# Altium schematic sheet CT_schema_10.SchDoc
size 389 x 278 mm
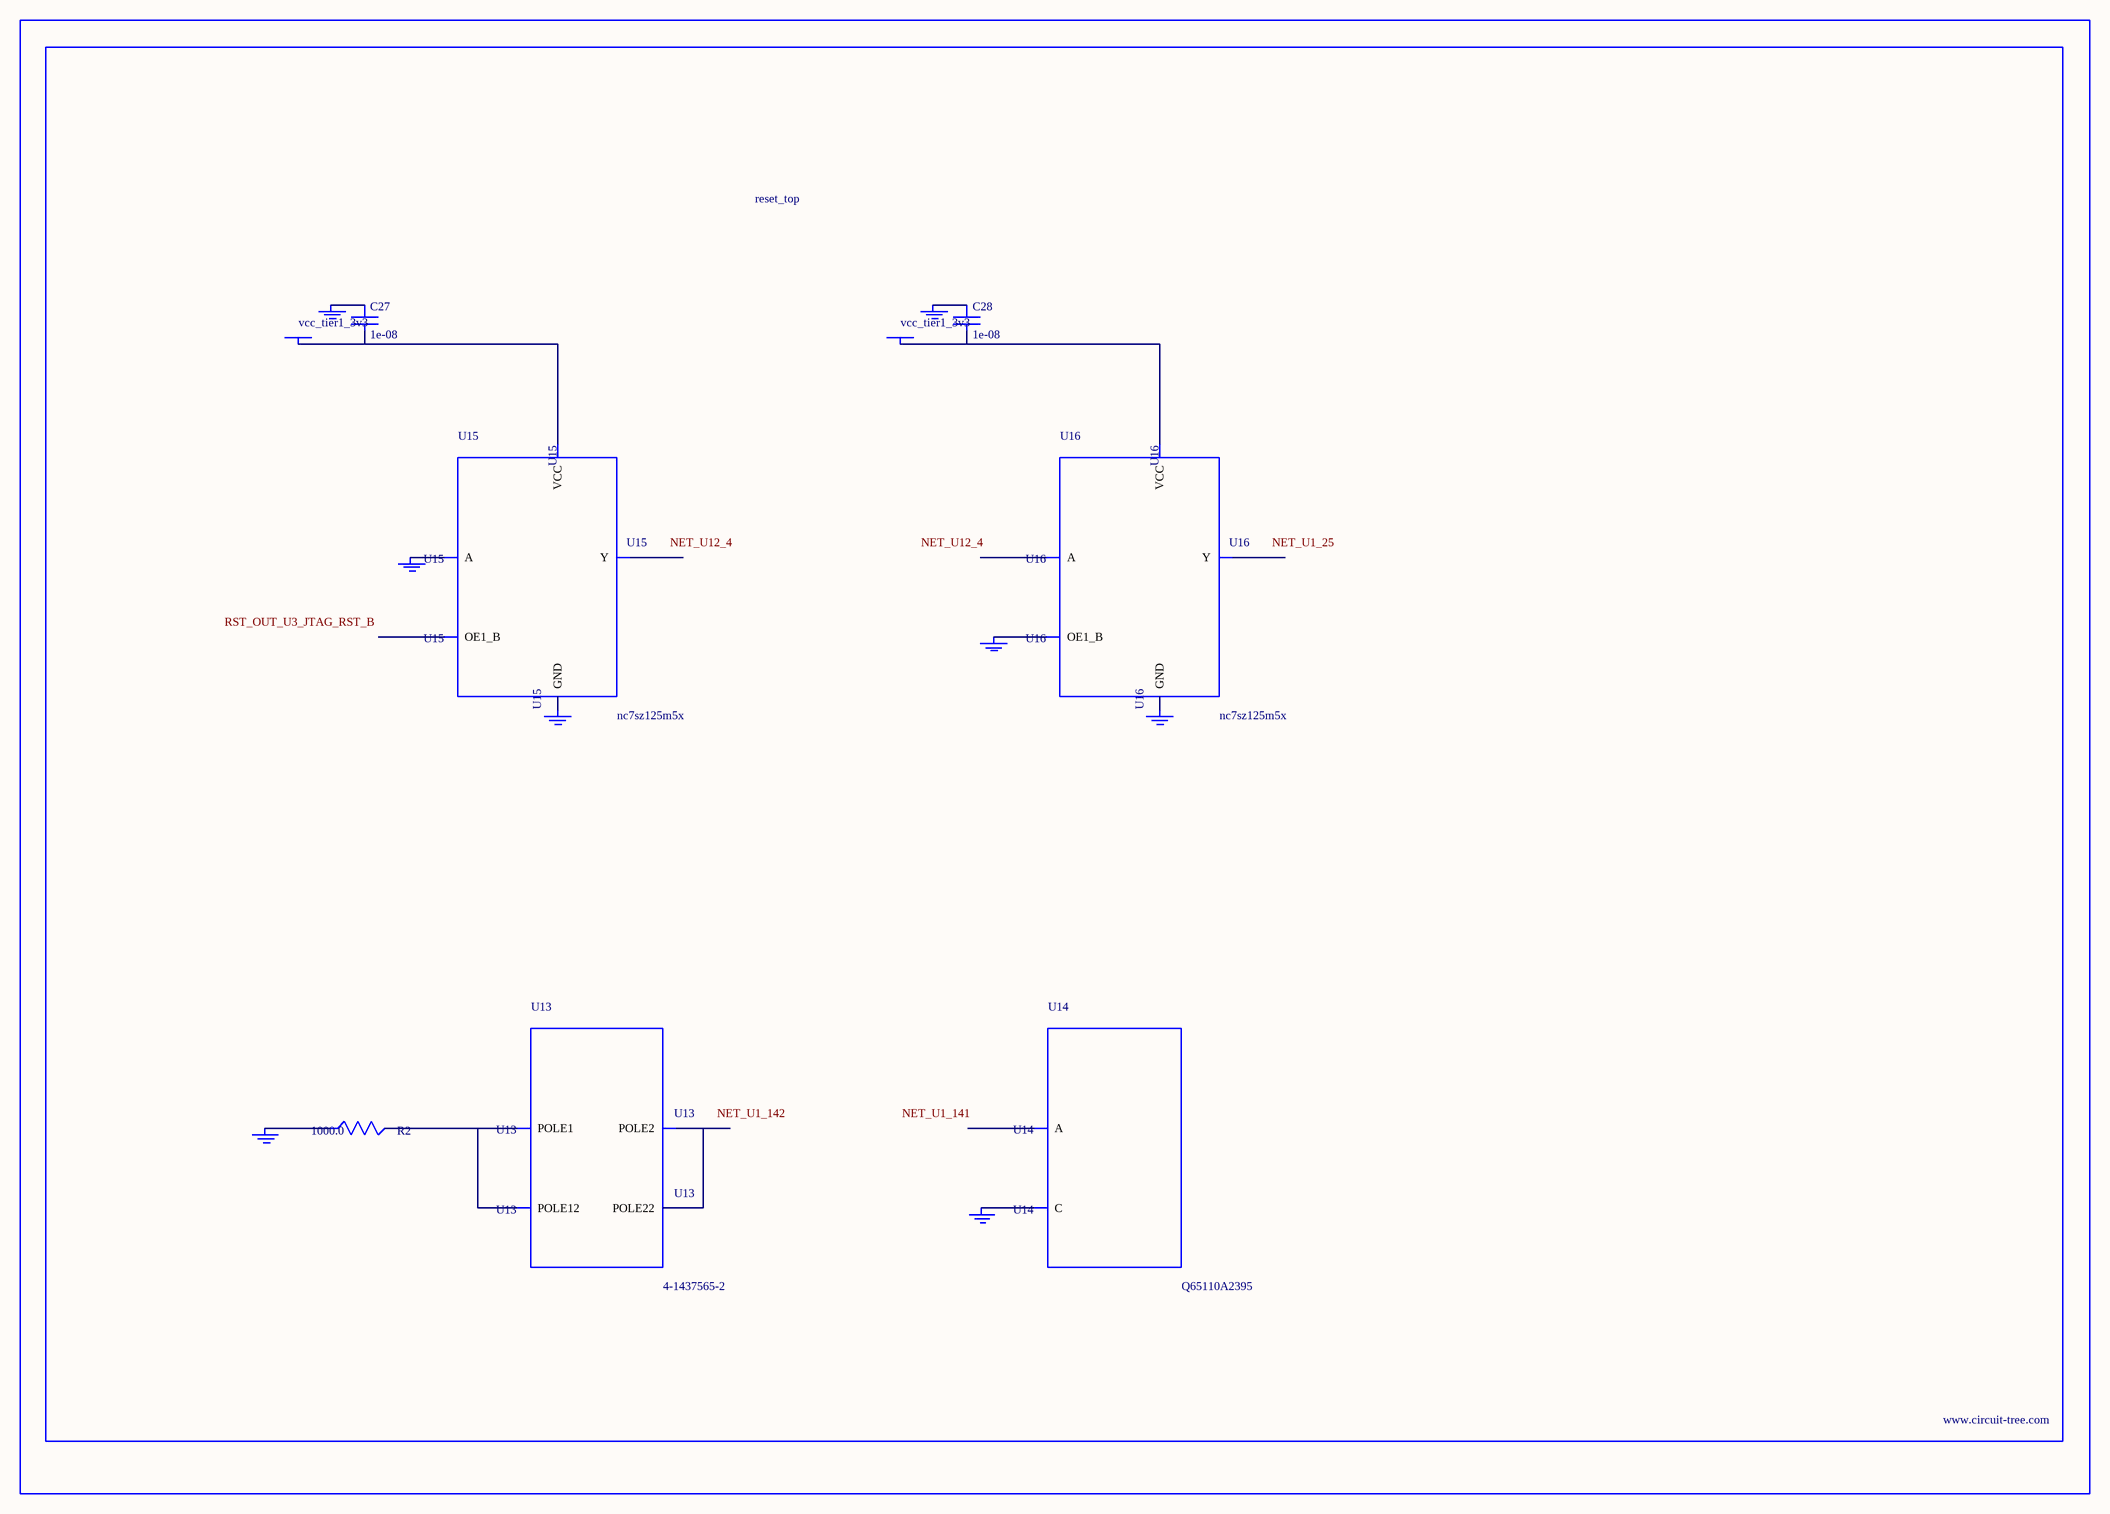
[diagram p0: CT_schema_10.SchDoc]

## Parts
BORDER9  (no value)
C27  1e-08  [C0402]
C28  1e-08  [C0402]
GND_INSTANCE_9_0  (no value)
GND_INSTANCE_9_1  (no value)
GND_INSTANCE_9_2  (no value)
GND_INSTANCE_9_3  (no value)
GND_INSTANCE_9_4  (no value)
GND_INSTANCE_9_5  (no value)
GND_INSTANCE_9_6  (no value)
GND_INSTANCE_9_7  (no value)
POWER_INSTANCE_9_0  vcc_tier1_3v3
POWER_INSTANCE_9_1  vcc_tier1_3v3
R2  1000.0  [R0603]
U13  4-1437565-2  [SW_4-1437565-2]
U14  Q65110A2395  [LGM67K-G1J2-24-Z]
U15  nc7sz125m5x  [NC7SZ125M5X]
U16  nc7sz125m5x  [NC7SZ125M5X]

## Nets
NetC27_1: C27.1 GND_INSTANCE_9_2.0(GND)
NetC27_2: C27.2 POWER_INSTANCE_9_0.0(PWR) U15.5(VCC)
NetC28_1: C28.1 GND_INSTANCE_9_5.0(GND)
NetC28_2: C28.2 POWER_INSTANCE_9_1.0(PWR) U16.5(VCC)
NetGND_INSTANCE_9_0_0: GND_INSTANCE_9_0.0(GND) R2.1
NetGND_INSTANCE_9_1_0: GND_INSTANCE_9_1.0(GND) U14.C
NetGND_INSTANCE_9_3_0: GND_INSTANCE_9_3.0(GND) U15.2(A)
NetGND_INSTANCE_9_4_0: GND_INSTANCE_9_4.0(GND) U15.3(GND)
NetGND_INSTANCE_9_6_0: GND_INSTANCE_9_6.0(GND) U16.1(OE1_B)
NetGND_INSTANCE_9_7_0: GND_INSTANCE_9_7.0(GND) U16.3(GND)
NetR2_2: R2.2 U13.1(POLE1) U13.2(POLE12)
NetU13_3: U13.3(POLE2) U13.4(POLE22)

Not connected (* = marked no-connect by the designer): U14 A; U15 1(OE1_B) 4(Y); U16 2(A) 4(Y)

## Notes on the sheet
- Labels drawn without touching a wire or pin: NET_U1_25, NET_U1_141, NET_U1_142, NET_U12_4, RST_OUT_U3_JTAG_RST_B

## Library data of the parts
BORDER9 = BORDER_PAGE9
C27 C28 = C0402C103K3RAC
GND_INSTANCE_9_0-GND_INSTANCE_9_7 = GND
POWER_INSTANCE_9_0 POWER_INSTANCE_9_1 = PWR
R2 = RC0603JR-071KL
